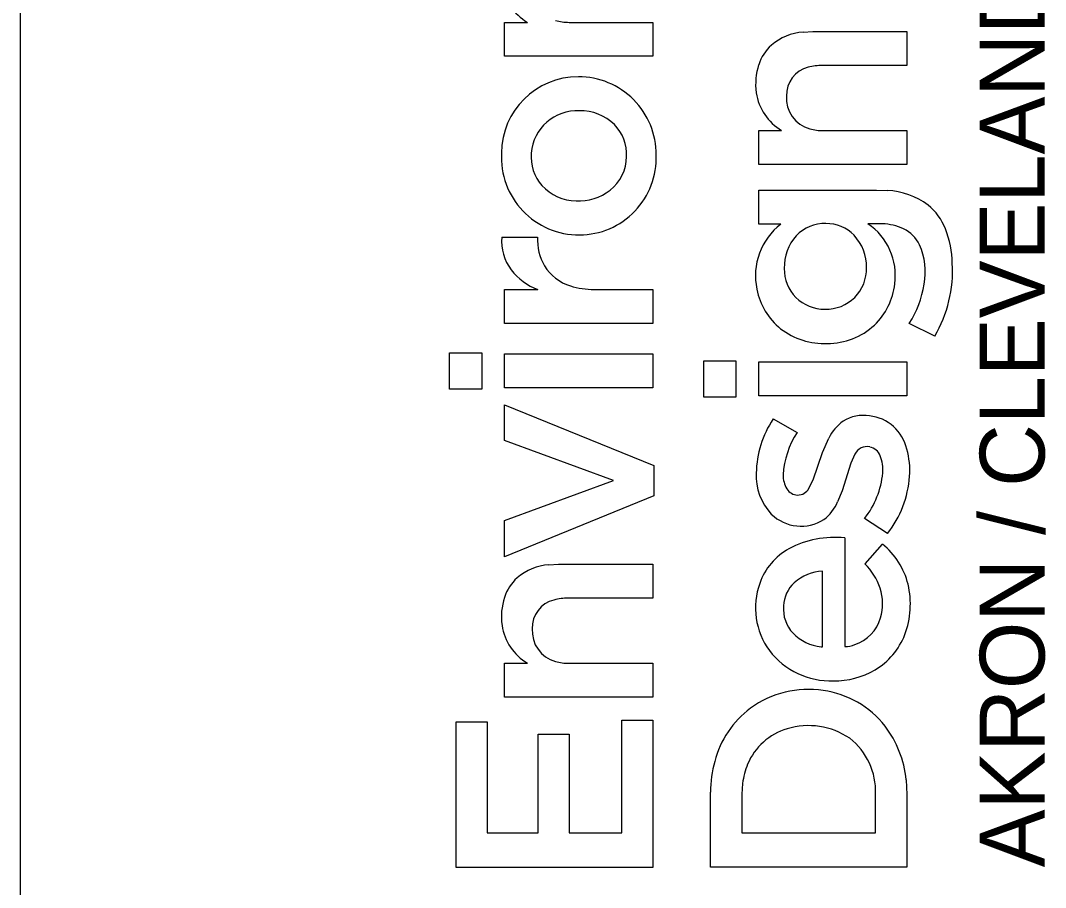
# Model space of a CAD drawing. Extents: x -0.5 to 34, y 0 to 22.
# Drawn here: x 32 to 32.901, y 3.12 to 3.882 of the extents above; entities that cross this region are included whole.
import ezdxf

# ---------------------------------------------------------------- set-up
doc = ezdxf.new("R2010")
doc.units = 0
doc.layers.add('SH_Border', color=7, linetype='Continuous')
doc.layers.add('SH_Data', color=7, linetype='Continuous')

msp = doc.modelspace()

# ---------------------------------------------------------------- linework, layer by layer
at = {"layer": 'SH_Border'}
msp.add_line((32, 0.5), (32, 21.5), dxfattribs=at)
at = {"layer": 'SH_Data'}
for p, q in [((32.42542, 3.88066), (32.44552, 3.88071)), ((32.42542, 3.85086), (32.42542, 3.88066)), ((32.48222, 3.88071), (32.55569, 3.88071)), ((32.55569, 3.88071), (32.55571, 3.85096)), ((32.68784, 3.8722), (32.69634, 3.87266)), ((32.69634, 3.87266), (32.77916, 3.87266)), ((32.77916, 3.87266), (32.77917, 3.84287)), ((32.55571, 3.85096), (32.42542, 3.85086)), ((32.77917, 3.84287), (32.70485, 3.8428)), ((32.64888, 3.7855), (32.66897, 3.78555)), ((32.64888, 3.75569), (32.64888, 3.7855)), ((32.70568, 3.78555), (32.77915, 3.78555)), ((32.77915, 3.78555), (32.77917, 3.75579)), ((32.77917, 3.75579), (32.64888, 3.75569)), ((32.6489, 3.70336), (32.64889, 3.73322)), ((32.64889, 3.73322), (32.75236, 3.73322)), ((32.75236, 3.73322), (32.76191, 3.73285)), ((32.66836, 3.70336), (32.6489, 3.70336)), ((32.75763, 3.70356), (32.74487, 3.70361)), ((32.42299, 3.69193), (32.45454, 3.69193)), ((32.42542, 3.64577), (32.45473, 3.64579)), ((32.42542, 3.61593), (32.42542, 3.64577)), ((32.50413, 3.64581), (32.55571, 3.64573)), ((32.55571, 3.64573), (32.55565, 3.61593)), ((32.55565, 3.61593), (32.42542, 3.61593)), ((32.8036, 3.60491), (32.7812, 3.61598)), ((32.37705, 3.55818), (32.37705, 3.59026)), ((32.37705, 3.59026), (32.40543, 3.59026)), ((32.40543, 3.59026), (32.40543, 3.55818)), ((32.42542, 3.55942), (32.42542, 3.58928)), ((32.42542, 3.58928), (32.55571, 3.58928)), ((32.55571, 3.58928), (32.55571, 3.55942)), ((32.60051, 3.55111), (32.60051, 3.58319)), ((32.60051, 3.58319), (32.62889, 3.58319)), ((32.62889, 3.58319), (32.62889, 3.55111)), ((32.64888, 3.55234), (32.64888, 3.5822)), ((32.64888, 3.5822), (32.77917, 3.5822)), ((32.77917, 3.5822), (32.77917, 3.55234)), ((32.55571, 3.55942), (32.42542, 3.55942)), ((32.40543, 3.55818), (32.37705, 3.55818)), ((32.62889, 3.55111), (32.60051, 3.55111)), ((32.77917, 3.55234), (32.64888, 3.55234)), ((32.42542, 3.51327), (32.42542, 3.5446)), ((32.42542, 3.5446), (32.5567, 3.4913)), ((32.66151, 3.53207), (32.68268, 3.52025)), ((32.70483, 3.50258), (32.71036, 3.51526)), ((32.52117, 3.47798), (32.42542, 3.51327)), ((32.69675, 3.47868), (32.70483, 3.50258)), ((32.73342, 3.50101), (32.72985, 3.4933)), ((32.5567, 3.4913), (32.5567, 3.46441)), ((32.72985, 3.4933), (32.72213, 3.46882)), ((32.42542, 3.44294), (32.52117, 3.47798)), ((32.69299, 3.47117), (32.69675, 3.47868)), ((32.72213, 3.46882), (32.71822, 3.45921)), ((32.5567, 3.46441), (32.42542, 3.41086)), ((32.42542, 3.41086), (32.42542, 3.44294)), ((32.76214, 3.43141), (32.74198, 3.44469)), ((32.72453, 3.42747), (32.72463, 3.33195)), ((32.74228, 3.40465), (32.75768, 3.422)), ((32.46439, 3.40397), (32.47289, 3.40443)), ((32.47289, 3.40443), (32.55571, 3.40443)), ((32.55571, 3.40443), (32.55571, 3.37465)), ((32.70489, 3.33182), (32.70489, 3.39834)), ((32.55571, 3.37465), (32.4814, 3.37457)), ((32.70361, 3.33165), (32.70489, 3.33182)), ((32.42542, 3.31728), (32.44552, 3.31733)), ((32.42542, 3.28747), (32.42542, 3.31728)), ((32.48222, 3.31733), (32.55569, 3.31733)), ((32.55569, 3.31733), (32.55571, 3.28756)), ((32.55571, 3.28756), (32.42542, 3.28747)), ((32.38298, 3.13791), (32.38298, 3.26598)), ((32.38298, 3.26598), (32.41012, 3.26598)), ((32.41012, 3.26598), (32.41012, 3.16827)), ((32.52857, 3.16827), (32.52857, 3.26722)), ((32.52857, 3.26722), (32.55571, 3.26722)), ((32.55571, 3.26722), (32.55571, 3.13791)), ((32.45503, 3.16827), (32.45503, 3.25488)), ((32.45503, 3.25488), (32.48218, 3.25488)), ((32.48218, 3.25488), (32.48218, 3.16827)), ((32.63465, 3.21178), (32.63407, 3.2023)), ((32.77847, 3.21497), (32.77917, 3.2021)), ((32.60643, 3.13799), (32.60644, 3.204)), ((32.63407, 3.2023), (32.63407, 3.16838)), ((32.75149, 3.16834), (32.75153, 3.20239)), ((32.77917, 3.2021), (32.77917, 3.138)), ((32.41012, 3.16827), (32.45503, 3.16827)), ((32.48218, 3.16827), (32.52857, 3.16827)), ((32.63407, 3.16838), (32.75149, 3.16834)), ((32.55571, 3.13791), (32.38298, 3.13791)), ((32.77917, 3.138), (32.60643, 3.13799))]:
    msp.add_line(p, q, dxfattribs=at)
for points in [[(32.42542, 3.85086), (32.42542, 3.88066), (32.44552, 3.88071)], [(32.48222, 3.88071), (32.55569, 3.88071), (32.55571, 3.85096), (32.42542, 3.85086)], [(32.68784, 3.8722), (32.69634, 3.87266), (32.77916, 3.87266), (32.77917, 3.84287), (32.70485, 3.8428)], [(32.64888, 3.75569), (32.64888, 3.7855), (32.66897, 3.78555)], [(32.70568, 3.78555), (32.77915, 3.78555), (32.77917, 3.75579), (32.64888, 3.75569)], [(32.66836, 3.70336), (32.6489, 3.70336), (32.64889, 3.73322), (32.75236, 3.73322), (32.76191, 3.73285)], [(32.75763, 3.70356), (32.74487, 3.70361)], [(32.42299, 3.69193), (32.45454, 3.69193)], [(32.50413, 3.64581), (32.55571, 3.64573), (32.55565, 3.61593), (32.42542, 3.61593)], [(32.42542, 3.61593), (32.42542, 3.64577), (32.45473, 3.64579)], [(32.8036, 3.60491), (32.7812, 3.61598)], [(32.66151, 3.53207), (32.68268, 3.52025)], [(32.69299, 3.47117), (32.69675, 3.47868), (32.70483, 3.50258), (32.71036, 3.51526)], [(32.73342, 3.50101), (32.72985, 3.4933), (32.72213, 3.46882), (32.71822, 3.45921)], [(32.76214, 3.43141), (32.74198, 3.44469)], [(32.72453, 3.42747), (32.72463, 3.33195)], [(32.74228, 3.40465), (32.75768, 3.422)], [(32.46439, 3.40397), (32.47289, 3.40443), (32.55571, 3.40443), (32.55571, 3.37465), (32.4814, 3.37457)], [(32.70361, 3.33165), (32.70489, 3.33182), (32.70489, 3.39834)], [(32.42542, 3.28747), (32.42542, 3.31728), (32.44552, 3.31733)], [(32.48222, 3.31733), (32.55569, 3.31733), (32.55571, 3.28756), (32.42542, 3.28747)], [(32.77847, 3.21497), (32.77917, 3.2021), (32.77917, 3.138), (32.60643, 3.13799)], [(32.63465, 3.21178), (32.63407, 3.2023), (32.63407, 3.16838), (32.75149, 3.16834), (32.75153, 3.20239)], [(32.60643, 3.13799), (32.60644, 3.204)]]:
    msp.add_lwpolyline(points, dxfattribs=at)
for points in [[(32.37705, 3.55818), (32.37705, 3.59026), (32.40543, 3.59026), (32.40543, 3.55818)], [(32.42542, 3.55942), (32.42542, 3.58928), (32.55571, 3.58928), (32.55571, 3.55942)], [(32.60051, 3.55111), (32.60051, 3.58319), (32.62889, 3.58319), (32.62889, 3.55111)], [(32.64888, 3.55234), (32.64888, 3.5822), (32.77917, 3.5822), (32.77917, 3.55234)], [(32.42542, 3.41086), (32.42542, 3.44294), (32.52117, 3.47798), (32.42542, 3.51327), (32.42542, 3.5446), (32.5567, 3.4913), (32.5567, 3.46441)], [(32.38298, 3.13791), (32.38298, 3.26598), (32.41012, 3.26598), (32.41012, 3.16827), (32.45503, 3.16827), (32.45503, 3.25488), (32.48218, 3.25488), (32.48218, 3.16827), (32.52857, 3.16827), (32.52857, 3.26722), (32.55571, 3.26722), (32.55571, 3.13791)]]:
    msp.add_lwpolyline(points, close=True, dxfattribs=at)
for centre, radius, start, end in [((32.47027, 3.92141), 0.04763, 188.96462, 238.69865), ((32.47027, 3.92141), 0.04763, 188.96462, 238.69865), ((32.48183, 3.92286), 0.04215, 254.08913, 270.52838), ((32.48183, 3.92286), 0.04215, 254.08913, 270.52838), ((32.69216, 3.82251), 0.04988, 94.97056, 130.22484), ((32.69216, 3.82251), 0.04988, 94.97056, 130.22484), ((32.68694, 3.83085), 0.04016, 132.22383, 161.68229), ((32.68694, 3.83085), 0.04016, 132.22383, 161.68229), ((32.70217, 3.82642), 0.05602, 162.27398, 187.79173), ((32.70217, 3.82642), 0.05602, 162.27398, 187.79173), ((32.69828, 3.81689), 0.02498, 103.68683, 182.21395), ((32.69828, 3.81689), 0.02498, 103.68683, 182.21395), ((32.70453, 3.79679), 0.04601, 89.60515, 105.33026), ((32.70453, 3.79679), 0.04601, 89.60515, 105.33026), ((32.49014, 3.76543), 0.0674, 89.84756, 179.64047), ((32.49014, 3.76543), 0.0674, 89.84756, 179.64047), ((32.49057, 3.76474), 0.0681, 359.54009, 90.21138), ((32.49057, 3.76474), 0.0681, 359.54009, 90.21138), ((32.69372, 3.82624), 0.04763, 188.96462, 238.69865), ((32.69372, 3.82624), 0.04763, 188.96462, 238.69865), ((32.7008, 3.81381), 0.02757, 175.58441, 255.13816), ((32.7008, 3.81381), 0.02757, 175.58441, 255.13816), ((32.48923, 3.76263), 0.0404, 87.04809, 175.57259), ((32.48923, 3.76263), 0.0404, 87.04809, 175.57259), ((32.49204, 3.75999), 0.04299, 45.84264, 90.98008), ((32.49204, 3.75999), 0.04299, 45.84264, 90.98008), ((32.49458, 3.76421), 0.03821, 357.88569, 44.15902), ((32.49458, 3.76421), 0.03821, 357.88569, 44.15902), ((32.70529, 3.82769), 0.04215, 254.08913, 270.52838), ((32.70529, 3.82769), 0.04215, 254.08913, 270.52838), ((32.49083, 3.76209), 0.06819, 176.8344, 270.40384), ((32.49083, 3.76209), 0.06819, 176.8344, 270.40384), ((32.48729, 3.7625), 0.03848, 175.15378, 221.14706), ((32.48729, 3.7625), 0.03848, 175.15378, 221.14706), ((32.49123, 3.76139), 0.06749, 270.06243, 2.37759), ((32.49123, 3.76139), 0.06749, 270.06243, 2.37759), ((32.49446, 3.76318), 0.0383, 308.28936, 359.43468), ((32.49446, 3.76318), 0.0383, 308.28936, 359.43468), ((32.48919, 3.76607), 0.04228, 223.09994, 268.80895), ((32.48919, 3.76607), 0.04228, 223.09994, 268.80895), ((32.49096, 3.7679), 0.04418, 266.56515, 308.06078), ((32.49096, 3.7679), 0.04418, 266.56515, 308.06078), ((32.75907, 3.66789), 0.06503, 53.40344, 87.49062), ((32.75907, 3.66789), 0.06503, 53.40344, 87.49062), ((32.76517, 3.68039), 0.05141, 21.60748, 50.5577), ((32.76517, 3.68039), 0.05141, 21.60748, 50.5577), ((32.70292, 3.65813), 0.05692, 127.37482, 192.22468), ((32.70292, 3.65813), 0.05692, 127.37482, 192.22468), ((32.70693, 3.66927), 0.0346, 88.47302, 136.42562), ((32.70693, 3.66927), 0.0346, 88.47302, 136.42562), ((32.70814, 3.66963), 0.03424, 44.27195, 90.47623), ((32.70814, 3.66963), 0.03424, 44.27195, 90.47623), ((32.71421, 3.65829), 0.05472, 352.1125, 55.92295), ((32.71421, 3.65829), 0.05472, 352.1125, 55.92295), ((32.75666, 3.65725), 0.04633, 65.01687, 88.8011), ((32.75666, 3.65725), 0.04633, 65.01687, 88.8011), ((32.7626, 3.67155), 0.03085, 26.26808, 63.80301), ((32.7626, 3.67155), 0.03085, 26.26808, 63.80301), ((32.73069, 3.66714), 0.08835, 1.15143, 21.3627), ((32.73069, 3.66714), 0.08835, 1.15143, 21.3627), ((32.46616, 3.68882), 0.04329, 175.87313, 216.34747), ((32.46616, 3.68882), 0.04329, 175.87313, 216.34747), ((32.50087, 3.68948), 0.04639, 176.9688, 209.60636), ((32.50087, 3.68948), 0.04639, 176.9688, 209.60636), ((32.71141, 3.66602), 0.0401, 137.46739, 182.33237), ((32.71141, 3.66602), 0.0401, 137.46739, 182.33237), ((32.70368, 3.666), 0.03996, 358.57141, 43.53765), ((32.70368, 3.666), 0.03996, 358.57141, 43.53765), ((32.73565, 3.66154), 0.05953, 349.30734, 23.43071), ((32.73565, 3.66154), 0.05953, 349.30734, 23.43071), ((32.70538, 3.66244), 0.11383, 329.6388, 3.25998), ((32.70538, 3.66244), 0.11383, 329.6388, 3.25998), ((32.47466, 3.69716), 0.05511, 218.09809, 248.7907), ((32.47466, 3.69716), 0.05511, 218.09809, 248.7907), ((32.49514, 3.68814), 0.04079, 211.94466, 253.2028), ((32.49514, 3.68814), 0.04079, 211.94466, 253.2028), ((32.70645, 3.6637), 0.03511, 178.88208, 271.08374), ((32.70645, 3.6637), 0.03511, 178.88208, 271.08374), ((32.70818, 3.66404), 0.03546, 268.27882, 1.55016), ((32.70818, 3.66404), 0.03546, 268.27882, 1.55016), ((32.50465, 3.7165), 0.07069, 252.46555, 269.57296), ((32.50465, 3.7165), 0.07069, 252.46555, 269.57296), ((32.70988, 3.65708), 0.05887, 313.74196, 353.8554), ((32.70988, 3.65708), 0.05887, 313.74196, 353.8554), ((32.70738, 3.66334), 0.08771, 327.31495, 351.57478), ((32.70738, 3.66334), 0.08771, 327.31495, 351.57478), ((32.70463, 3.65696), 0.05837, 190.75182, 231.28919), ((32.70463, 3.65696), 0.05837, 190.75182, 231.28919), ((32.70954, 3.65901), 0.06051, 269.6361, 312.70877), ((32.70954, 3.65901), 0.06051, 269.6361, 312.70877), ((32.70632, 3.66112), 0.06269, 232.46061, 272.59022), ((32.70632, 3.66112), 0.06269, 232.46061, 272.59022), ((32.73636, 3.48258), 0.08973, 146.53104, 178.7571), ((32.73636, 3.48258), 0.08973, 146.53104, 178.7571), ((32.7406, 3.5026), 0.03263, 80.17192, 122.51969), ((32.7406, 3.5026), 0.03263, 80.17192, 122.51969), ((32.74278, 3.49824), 0.03667, 47.79344, 84.68918), ((32.74278, 3.49824), 0.03667, 47.79344, 84.68918), ((32.74661, 3.49713), 0.04053, 125.51182, 153.41595), ((32.74661, 3.49713), 0.04053, 125.51182, 153.41595), ((32.73788, 3.4946), 0.04267, 14.9966, 46.20632), ((32.73788, 3.4946), 0.04267, 14.9966, 46.20632), ((32.74519, 3.4789), 0.07495, 146.51121, 176.91007), ((32.74519, 3.4789), 0.07495, 146.51121, 176.91007), ((32.74384, 3.49631), 0.01143, 76.66094, 155.7053), ((32.74384, 3.49631), 0.01143, 76.66094, 155.7053), ((32.74397, 3.49511), 0.01256, 21.5098, 78.52618), ((32.74397, 3.49511), 0.01256, 21.5098, 78.52618), ((32.71044, 3.48674), 0.07121, 355.83062, 15.39138), ((32.71044, 3.48674), 0.07121, 355.83062, 15.39138), ((32.72592, 3.48766), 0.03209, 354.57264, 22.06805), ((32.72592, 3.48766), 0.03209, 354.57264, 22.06805), ((32.69666, 3.48238), 0.05005, 177.53659, 222.79318), ((32.69666, 3.48238), 0.05005, 177.53659, 222.79318), ((32.6931, 3.48233), 0.02276, 178.47474, 211.08679), ((32.6931, 3.48233), 0.02276, 178.47474, 211.08679), ((32.68248, 3.49149), 0.0757, 321.81101, 354.79685), ((32.68248, 3.49149), 0.0757, 321.81101, 354.79685), ((32.68952, 3.4882), 0.09219, 321.9777, 355.87384), ((32.68952, 3.4882), 0.09219, 321.9777, 355.87384), ((32.68331, 3.4767), 0.01148, 212.23676, 268.37769), ((32.68331, 3.4767), 0.01148, 212.23676, 268.37769), ((32.68342, 3.47589), 0.01067, 267.71603, 333.73375), ((32.68342, 3.47589), 0.01067, 267.71603, 333.73375), ((32.68098, 3.4758), 0.04077, 308.08772, 335.98736), ((32.68098, 3.4758), 0.04077, 308.08772, 335.98736), ((32.68599, 3.47535), 0.0375, 225.98539, 302.47965), ((32.68599, 3.47535), 0.0375, 225.98539, 302.47965), ((32.7152, 3.34414), 0.08384, 83.61499, 118.28755), ((32.7152, 3.34414), 0.08384, 83.61499, 118.28755), ((32.70239, 3.36906), 0.05583, 118.83082, 160.62438), ((32.70239, 3.36906), 0.05583, 118.83082, 160.62438), ((32.71744, 3.37167), 0.06443, 13.53365, 51.36148), ((32.71744, 3.37167), 0.06443, 13.53365, 51.36148), ((32.46871, 3.35428), 0.04988, 94.96958, 130.22249), ((32.46871, 3.35428), 0.04988, 94.96958, 130.22249), ((32.70785, 3.35609), 0.04235, 94.00805, 130.88169), ((32.70785, 3.35609), 0.04235, 94.00805, 130.88169), ((32.70378, 3.36556), 0.05486, 19.03571, 45.44059), ((32.70378, 3.36556), 0.05486, 19.03571, 45.44059), ((32.46348, 3.36263), 0.04015, 132.22192, 161.68183), ((32.46348, 3.36263), 0.04015, 132.22192, 161.68183), ((32.71041, 3.36612), 0.06437, 160.52012, 215.78311), ((32.71041, 3.36612), 0.06437, 160.52012, 215.78311), ((32.70048, 3.36628), 0.02985, 132.98507, 177.179), ((32.70048, 3.36628), 0.02985, 132.98507, 177.179), ((32.71069, 3.3697), 0.047, 344.60586, 17.007), ((32.71069, 3.3697), 0.047, 344.60586, 17.007), ((32.70635, 3.36921), 0.07579, 339.3542, 13.37853), ((32.70635, 3.36921), 0.07579, 339.3542, 13.37853), ((32.47872, 3.35819), 0.05601, 162.27355, 187.79185), ((32.47872, 3.35819), 0.05601, 162.27355, 187.79185), ((32.47482, 3.34867), 0.02498, 103.68646, 182.21874), ((32.47482, 3.34867), 0.02498, 103.68646, 182.21874), ((32.48108, 3.32856), 0.04601, 89.60494, 105.3284), ((32.48108, 3.32856), 0.04601, 89.60494, 105.3284), ((32.7017, 3.36503), 0.03115, 175.00126, 223.28301), ((32.7017, 3.36503), 0.03115, 175.00126, 223.28301), ((32.7224, 3.36715), 0.03504, 288.00773, 343.55078), ((32.7224, 3.36715), 0.03504, 288.00773, 343.55078), ((32.47026, 3.35802), 0.04762, 188.96199, 238.70369), ((32.47026, 3.35802), 0.04762, 188.96199, 238.70369), ((32.47735, 3.34558), 0.02756, 175.58538, 255.14386), ((32.47735, 3.34558), 0.02756, 175.58538, 255.14386), ((32.70891, 3.37363), 0.04231, 225.06188, 262.79738), ((32.70891, 3.37363), 0.04231, 225.06188, 262.79738), ((32.71894, 3.3652), 0.0626, 300.94269, 338.73225), ((32.71894, 3.3652), 0.0626, 300.94269, 338.73225), ((32.72474, 3.35216), 0.02021, 269.7003, 294.8711), ((32.72474, 3.35216), 0.02021, 269.7003, 294.8711), ((32.71253, 3.37054), 0.06872, 217.74516, 271.65431), ((32.71253, 3.37054), 0.06872, 217.74516, 271.65431), ((32.48183, 3.35948), 0.04215, 254.09162, 270.52835), ((32.48183, 3.35948), 0.04215, 254.09162, 270.52835), ((32.71549, 3.37241), 0.07056, 269.20477, 300.33412), ((32.71549, 3.37241), 0.07056, 269.20477, 300.33412), ((32.69229, 3.20792), 0.08641, 81.19402, 125.99844), ((32.69229, 3.20792), 0.08641, 81.19402, 125.99844), ((32.69458, 3.21132), 0.08272, 37.85208, 82.40204), ((32.69458, 3.21132), 0.08272, 37.85208, 82.40204), ((32.69387, 3.20893), 0.08654, 127.23621, 165.14796), ((32.69387, 3.20893), 0.08654, 127.23621, 165.14796), ((32.69279, 3.19862), 0.06389, 55.67272, 107.20935), ((32.69279, 3.19862), 0.06389, 55.67272, 107.20935), ((32.68586, 3.20567), 0.09308, 5.73329, 37.30396), ((32.68586, 3.20567), 0.09308, 5.73329, 37.30396), ((32.68893, 3.20782), 0.05398, 106.18808, 157.38609), ((32.68893, 3.20782), 0.05398, 106.18808, 157.38609), ((32.69291, 3.20499), 0.05867, 357.46616, 52.26647), ((32.69291, 3.20499), 0.05867, 357.46616, 52.26647), ((32.71426, 3.20281), 0.10783, 164.7861, 179.37039), ((32.71426, 3.20281), 0.10783, 164.7861, 179.37039), ((32.69829, 3.20389), 0.06412, 157.35705, 172.92755), ((32.69829, 3.20389), 0.06412, 157.35705, 172.92755)]:
    msp.add_arc(centre, radius, start, end, dxfattribs=at)

# ---------------------------------------------------------------- texts
msp.add_text('AKRON / CLEVELAND / COLUMBUS', height=0.056969, rotation=90, dxfattribs=at).set_placement((32.90012, 3.138))

doc.saveas('drawing.dxf')
